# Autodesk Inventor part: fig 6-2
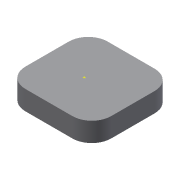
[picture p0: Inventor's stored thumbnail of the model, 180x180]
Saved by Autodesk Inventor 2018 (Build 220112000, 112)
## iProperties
Created: 2004-05
Part Number: fig 6-2
Document SubType Name: Modeling
Designer: CADCIM Technologies
Manufacturer: Standard
Standards Organization: Custom
Density: 1 g/cm^3
Material: Generic
Appearance: Default
Author: CADCIM Technologies
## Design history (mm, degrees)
sketch "Sketch1"
  geometry: L1 (0, 0)-(44.293, 0); L2 (44.293, 0)-(44.293, 42.442); L3 (44.293, 42.442)-(0, 42.442); L4 (0, 42.442)-(0, 0)
  constraints: 8 end point, 2 parallel, 1 horizontal, 1 perpendicular
extrude "Extrusion1" new body sketch "Sketch1" distance "d0" = 10; taper "d1" = 0 deg
fillet "Fillet1" dims "d2" = 10
sketch "Sketch2"
  geometry: 1 further point
sketch "Sketch3"
  geometry: L1 (10, 42.442)-(34.293, 42.442) reference; L2 (0, 10)-(0, 32.442) reference; L3 (34.293, 0)-(10, 0) reference; L4 (44.293, 32.442)-(44.293, 10) reference; A1 r 10 centre (34.293, 32.442) between (44.293, 32.442) and (34.293, 42.442) reference; A2 r 10 centre (10, 32.442) between (10, 42.442) and (0, 32.442) reference; A3 r 10 centre (10, 10) between (0, 10) and (10, 0) reference; A4 r 10 centre (34.293, 10) between (34.293, 0) and (44.293, 10) reference; 1 further point
workpoint "Work Point1"
body "Solid1"
